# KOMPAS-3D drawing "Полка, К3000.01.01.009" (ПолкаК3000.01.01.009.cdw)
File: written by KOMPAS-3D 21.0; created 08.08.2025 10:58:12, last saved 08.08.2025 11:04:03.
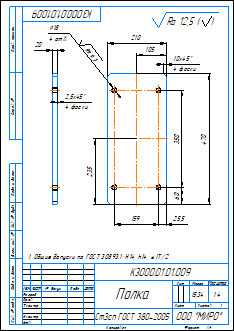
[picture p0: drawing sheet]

Sheet 1: A4, portrait

Document properties: Автор: admin; Знак неуказанной шероховатости: 4; Параметр неуказанной шероховатости: Ra 12,5; Масса: 15.343907; Полное имя файла: ..\Из трубы\Полка.m3d

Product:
- Part/product: Полка  | designation К3000.01.01.009
    Материал: Ст3сп ГОСТ 380-2005 (density 7850 kg/m3)
    Масса: 15.343907

Title block, sheet 1: Наименование: Полка; designation: К3000.01.01.009; Материал: Ст3сп ГОСТ 380-2005; Масса: 15,34; Количество листов документа: 1; organisation: ООО "МИРО"; Форматы листов документа: A4; stored path: C:\Users\ShavarinML\Desktop\Стапель\2D\ПолкаК3000.01.01.009.cdw

Views: Спереди 1, Спереди, Проекционный вид 2
Referenced files in C:\Users\ShavarinML\Desktop\Стапель\Из трубы\: Полка.m3d
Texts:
  Ra 6,3
  Ra 12,5
  Ra 12,5 ( )
  К3000.01.01.009 Полка
Dimensions and other numbers on the sheet: 20; 2,5; 4 фаски; 7; 210; 470; 105; 10; 25,5; 60; 159; 350; 235; 18; 4 отв.; 1:4; 1; 15,34

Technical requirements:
  Общие допуски по ГОСТ 30893.1: H14, h14,   IT/2.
